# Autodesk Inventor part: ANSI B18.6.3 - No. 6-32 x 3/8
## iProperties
Author: Elise Moss
Created: 2002-03
Part Number: ANSI B18.6.3 - No. 6-32 x 3/8
Catalog Web Link: file:///C:/Program%20Files/Autodesk/Inventor%205/Content/Ansi/index.htm?doNavigateId=BEF4238F-1434-4260-83BF-15166A2168DD|7767BEFBD7E811D4BA8200C04F798F98|true
Description: Slotted Flat Countersunk Head Machine Screw
Document SubType Name: Standard Catalog Part
Standard: ANSI B18.6.3 - No. 6-32 x 3/8
Designer: Elise Moss
CLASSIFICATION: 31161513 un/spsc
MANUFACTURER: ANSI Standard System
Control State: 0
Master: False
Checked Out: False
PropertySet Name: Design Tracking Control
Shininess: 64.0
Angle Display Precision: 2
Document Length Units: 11269
Document Angle Units: 11283
Document Time Units: 11279
Document Mass Units: 11290
Document Length Units Precision: 3
Document Angle Units Precision: 2
Compacted: False
PropertySet Name: _Private Model Information
Density: 0.0
Volumn: 0.0
Area: 0.0
PropertySet Name: Model Information
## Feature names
1. Base1
